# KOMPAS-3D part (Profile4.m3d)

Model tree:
1. Plane XY
2. Plane ZX
3. Plane ZY
4. X Axis
5. Y Axis
6. Z Axis
7. Origin
8. Sketch:1
9. Extrude:1
     Wall Thickness 1 = 1; Wall Thickness 2 = 8; Distance 1 = 2060; Distance 2 = 10
10. Sketch:2
11. Extrude:2
     Wall Thickness 1 = 1; Wall Thickness 2 = 8; Distance 1 = 111; Distance 2 = 10
12. Sketch:3
13. Three Point Plane:1
14. Extrude:3
     Wall Thickness 1 = 1; Wall Thickness 2 = 8; Distance 1 = 111; Distance 2 = 10

Referenced files in D:\Documents and Settings\kashirsky\Рабочий стол\Seminar\: Cottage_balcony.a3d
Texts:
  Steel DIN 17102
  Three Point Plane
  Plane at Angle
  Line and Point Plane
  Axis through Two Vertices
  Axis of Feature
  Axis of Conical Surface
  Axis through Edge
  Trim by Surface
  Trim by Sketch
  Feature with No History
  Intersection Axis of Two Planes
  Two Line Plane
  Line and Face Plane
  Bend by line
  Hole in sheet body
  Cut in sheet body
  Point in CM
  Linear Dimension from Line to Point
  Surface Finish Symbol
  Geometric Tolerance Symbol
  Leader #1
  Leader #2
  Leader #3
  Shape Deviations and Datum
  Node point number
  Mark of coordination axis
  Node point designation
  Mark/Reference designation with leader
  Mark/reference designation on line
  Mark/Reference designation without leader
